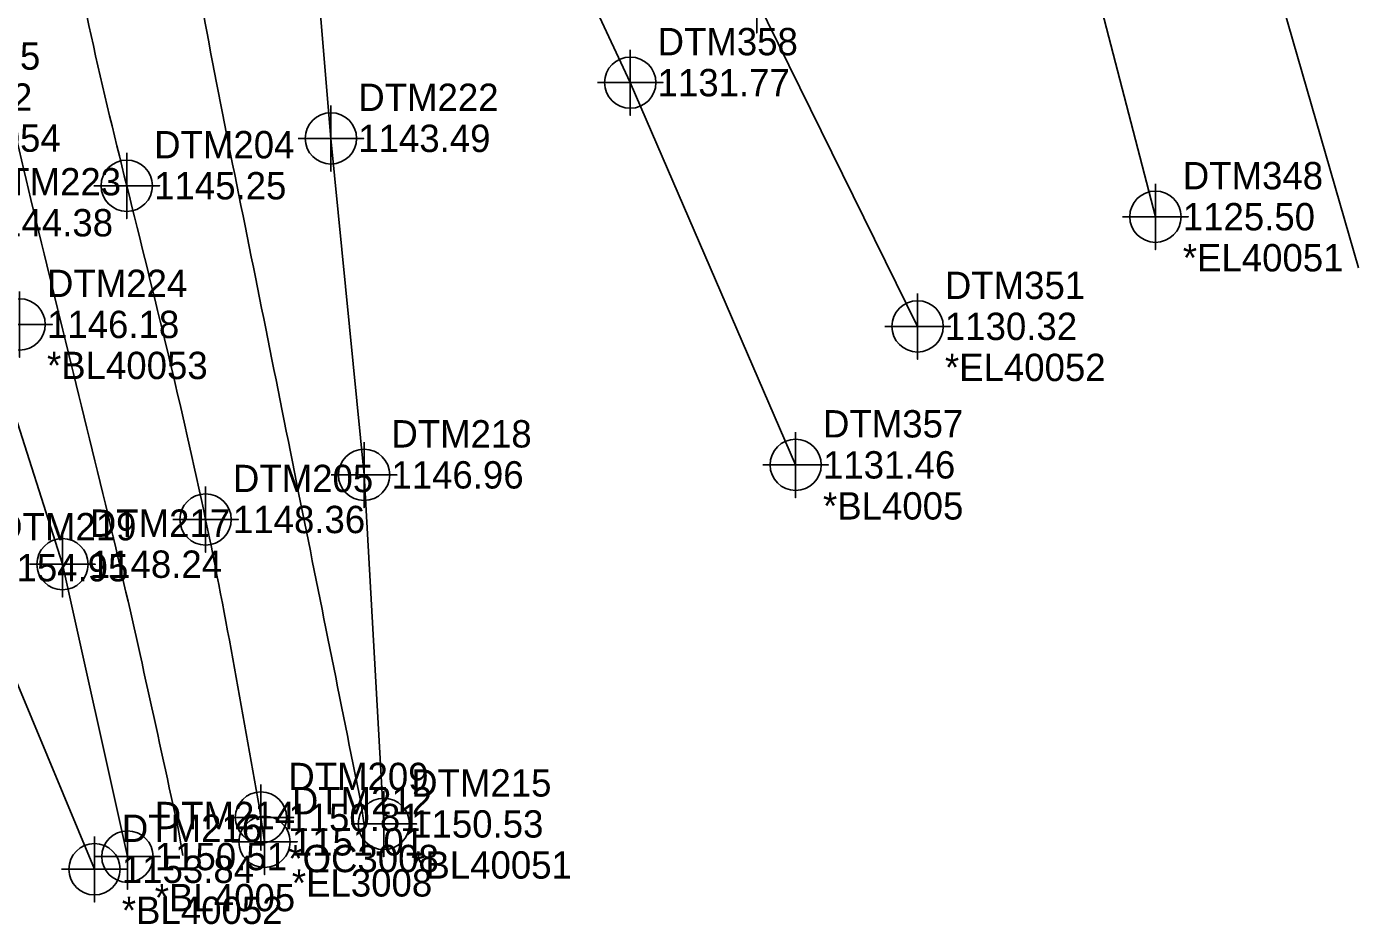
# Model space of a CAD drawing. Extents: x 1286409 to 1286829, y 857931 to 858308.
# Drawn here: x 1286511.7 to 1286633.4, y 857950.3 to 858032.3 of the extents above; entities that cross this region are included whole.
import ezdxf

# ---------------------------------------------------------------- set-up
doc = ezdxf.new("R2010")
doc.units = 0
for name, color, linetype in [('Exist DTM Breakline', 7, 'Continuous'), ('Exist DTM Breakline Cogo Comment', 7, 'Continuous'), ('Exist DTM Breakline Cogo Elevation', 7, 'Continuous'), ('Exist DTM Breakline Cogo Number', 7, 'Continuous'), ('Exist DTM Breakline Cogo Point CELL', 7, 'Continuous'), ('Exist DTM Crownline', 7, 'Continuous'), ('Exist DTM Crownline Cogo Comment', 7, 'Continuous'), ('Exist DTM Crownline Cogo Elevation', 7, 'Continuous'), ('Exist DTM Crownline Cogo Number', 7, 'Continuous'), ('Exist DTM Crownline Cogo Point CELL', 7, 'Continuous'), ('Exist Hydro Stream or Body of Water', 7, 'Continuous'), ('Exist Roads EOP', 7, 'Continuous')]:
    doc.layers.add(name, color=color, linetype=linetype)

msp = doc.modelspace()

# ---------------------------------------------------------------- linework, layer by layer
at = {"layer": 'Exist DTM Breakline'}
for points in [[(1286530.298, 858233.7), (1286543.261, 858195.881), (1286559.854, 858160.955), (1286563.292, 858147.427), (1286569.804, 858128.536), (1286569.528, 858112.107), (1286564.126, 858113.252), (1286558.412, 858113.755), (1286552.418, 858104.363), (1286554.757, 858095.462), (1286567.776, 858091.209), (1286569.105, 858068.653), (1286573.239, 858056.109), (1286586.738, 858049.307), (1286601.784, 858041.235), (1286607.702, 858042.424), (1286614.823, 858014.95)], [(1286520.872, 857956.475), (1286514.938, 857983.192), (1286504.975, 858014.397), (1286495.914, 858037.226), (1286486.828, 858061.942), (1286479.65, 858081.695), (1286469.24, 858100.695), (1286458.123, 858119.163), (1286445.852, 858131.468)], [(1286544.306, 857959.455), (1286542.498, 857991.356), (1286539.471, 858022.109), (1286538.051, 858038.904), (1286537.678, 858080.597), (1286539.403, 858085.731)], [(1286581.943, 857992.271), (1286566.826, 858027.199), (1286551.086, 858060.906), (1286539.718, 858085.149)], [(1286563.919, 858062.445), (1286578.38, 858034.745), (1286593.083, 858004.927)], [(1286517.862, 857955.312), (1286506.377, 857982.872), (1286493.003, 858017.794), (1286486.448, 857993.306), (1286467.899, 857993.131), (1286458.369, 858018.086), (1286470.547, 858031.105), (1286479.897, 858042.174), (1286469.015, 858060.288)]]:
    msp.add_lwpolyline(points, dxfattribs=at)
at = {"layer": 'Exist DTM Breakline Cogo Point CELL'}
for points in [[(1286578.38, 858037.745), (1286578.38, 858031.745), (1286578.38, 858034.745), (1286581.38, 858034.745), (1286575.38, 858034.745)], [(1286566.826, 858030.199), (1286566.826, 858024.199), (1286566.826, 858027.199), (1286569.826, 858027.199), (1286563.826, 858027.199)], [(1286539.471, 858025.109), (1286539.471, 858019.109), (1286539.471, 858022.109), (1286542.471, 858022.109), (1286536.471, 858022.109)], [(1286614.823, 858017.95), (1286614.823, 858011.95), (1286614.823, 858014.95), (1286617.823, 858014.95), (1286611.823, 858014.95)], [(1286511.023, 858008.106), (1286511.023, 858002.106), (1286511.023, 858005.106), (1286514.023, 858005.106), (1286508.023, 858005.106)], [(1286593.083, 858007.927), (1286593.083, 858001.927), (1286593.083, 858004.927), (1286596.083, 858004.927), (1286590.083, 858004.927)], [(1286542.498, 857994.356), (1286542.498, 857988.356), (1286542.498, 857991.356), (1286545.498, 857991.356), (1286539.498, 857991.356)], [(1286581.943, 857995.271), (1286581.943, 857989.271), (1286581.943, 857992.271), (1286584.943, 857992.271), (1286578.943, 857992.271)], [(1286514.938, 857986.192), (1286514.938, 857980.192), (1286514.938, 857983.192), (1286517.938, 857983.192), (1286511.938, 857983.192)], [(1286544.306, 857962.455), (1286544.306, 857956.455), (1286544.306, 857959.455), (1286547.306, 857959.455), (1286541.306, 857959.455)], [(1286520.872, 857959.475), (1286520.872, 857953.475), (1286520.872, 857956.475), (1286523.872, 857956.475), (1286517.872, 857956.475)], [(1286517.862, 857958.312), (1286517.862, 857952.312), (1286517.862, 857955.312), (1286520.862, 857955.312), (1286514.862, 857955.312)]]:
    msp.add_lwpolyline(points, dxfattribs=at)
for centre in [(1286566.826, 858027.199), (1286539.471, 858022.109), (1286614.823, 858014.95), (1286511.023, 858005.106), (1286593.083, 858004.927), (1286581.943, 857992.271), (1286542.498, 857991.356), (1286514.938, 857983.192), (1286544.306, 857959.455), (1286517.862, 857955.312), (1286520.872, 857956.475)]:
    msp.add_circle(centre, 2.344, dxfattribs=at)
at = {"layer": 'Exist DTM Crownline'}
msp.add_line((1286533.078, 857960.044), (1286533.401, 857957.819), dxfattribs=at)
msp.add_spline([(1286558.043, 858132.348), (1286548.721, 858127.222), (1286534.801, 858118.181), (1286523.71, 858102.686), (1286514.506, 858073.789), (1286514.745, 858047.233), (1286520.815, 858017.78), (1286528.017, 857987.278), (1286533.078, 857960.044)], degree=3, dxfattribs=at)
at = {"layer": 'Exist DTM Crownline Cogo Point CELL'}
for points in [[(1286520.815, 858020.78), (1286520.815, 858014.78), (1286520.815, 858017.78), (1286523.815, 858017.78), (1286517.815, 858017.78)], [(1286528.017, 857990.278), (1286528.017, 857984.278), (1286528.017, 857987.278), (1286531.017, 857987.278), (1286525.017, 857987.278)], [(1286533.078, 857963.044), (1286533.078, 857957.044), (1286533.078, 857960.044), (1286536.078, 857960.044), (1286530.078, 857960.044)], [(1286533.401, 857960.819), (1286533.401, 857954.819), (1286533.401, 857957.819), (1286536.401, 857957.819), (1286530.401, 857957.819)]]:
    msp.add_lwpolyline(points, dxfattribs=at)
for centre in [(1286520.815, 858017.78), (1286528.017, 857987.278), (1286533.078, 857960.044), (1286533.401, 857957.819)]:
    msp.add_circle(centre, 2.344, dxfattribs=at)
at = {"layer": 'Exist Hydro Stream or Body of Water'}
msp.add_lwpolyline([(1286633.369, 858010.272), (1286619.226, 858059.374), (1286604.574, 858088.843), (1286588.568, 858128.319), (1286577.591, 858159.308), (1286547.36, 858229.805), (1286531.042, 858265.146)], dxfattribs=at)
at = {"layer": 'Exist Roads EOP'}
for p, q in [((1286542.222, 857961.323), (1286542.518, 857959.301)), ((1286525.58, 857958.7), (1286525.934, 857956.558))]:
    msp.add_line(p, q, dxfattribs=at)
for points in [[(1286554.506, 858138.221), (1286544.419, 858134.401), (1286528.832, 858126.933), (1286512.047, 858109.768), (1286502.652, 858089.088), (1286501.393, 858072.897), (1286505.471, 858045.649), (1286512.056, 858016.522), (1286519.805, 857984.681), (1286525.58, 857958.7)], [(1286561.061, 858127.479), (1286553.633, 858121.854), (1286541.776, 858109.576), (1286533.023, 858097.553), (1286526.163, 858072.381), (1286525.732, 858049.679), (1286530.491, 858019.74), (1286536.523, 857989.722), (1286542.222, 857961.323)]]:
    msp.add_spline(points, degree=3, dxfattribs=at)

# ---------------------------------------------------------------- texts
at = {"layer": 'Exist DTM Breakline Cogo Comment'}
for s, p in [('*BL40054', (1286500.091, 858020.882)), ('*EL40051', (1286617.323, 858009.95)), ('*BL40053', (1286513.523, 858000.106)), ('*EL40052', (1286595.583, 857999.927)), ('*BL4005', (1286584.443, 857987.271)), ('*BL40051', (1286546.806, 857954.455)), ('*BL4005', (1286523.372, 857951.475)), ('*BL40052', (1286520.362, 857950.312))]:
    msp.add_text(s, height=2.5, dxfattribs=at).set_placement(p)
at = {"layer": 'Exist DTM Breakline Cogo Elevation'}
for s, p in [('1131.77', (1286569.326, 858025.949)), ('1143.72', (1286500.091, 858024.632)), ('1143.49', (1286541.971, 858020.859)), ('1125.50', (1286617.323, 858013.7)), ('1144.38', (1286507.475, 858013.147)), ('1146.18', (1286513.523, 858003.856)), ('1130.32', (1286595.583, 858003.677)), ('1131.46', (1286584.443, 857991.021)), ('1146.96', (1286544.998, 857990.106)), ('1148.24', (1286517.438, 857981.942)), ('1154.95', (1286508.877, 857981.622)), ('1150.53', (1286546.806, 857958.205)), ('1150.51', (1286523.372, 857955.225)), ('1153.84', (1286520.362, 857954.062))]:
    msp.add_text(s, height=2.5, dxfattribs=at).set_placement(p)
at = {"layer": 'Exist DTM Breakline Cogo Number'}
for s, p in [('DTM358', (1286569.326, 858029.699)), ('DTM225', (1286500.091, 858028.382)), ('DTM222', (1286541.971, 858024.609)), ('DTM348', (1286617.323, 858017.45)), ('DTM223', (1286507.475, 858016.897)), ('DTM224', (1286513.523, 858007.606)), ('DTM351', (1286595.583, 858007.427)), ('DTM357', (1286584.443, 857994.771)), ('DTM218', (1286544.998, 857993.856)), ('DTM217', (1286517.438, 857985.692)), ('DTM219', (1286508.877, 857985.372)), ('DTM215', (1286546.806, 857961.955)), ('DTM214', (1286523.372, 857958.975)), ('DTM216', (1286520.362, 857957.812))]:
    msp.add_text(s, height=2.5, dxfattribs=at).set_placement(p)
at = {"layer": 'Exist DTM Crownline Cogo Comment'}
for s, p in [('*OC3008', (1286535.578, 857955.044)), ('*EL3008', (1286535.901, 857952.819))]:
    msp.add_text(s, height=2.5, dxfattribs=at).set_placement(p)
at = {"layer": 'Exist DTM Crownline Cogo Elevation'}
for s, p in [('1145.25', (1286523.315, 858016.53)), ('1148.36', (1286530.517, 857986.028)), ('1150.81', (1286535.578, 857958.794)), ('1151.01', (1286535.901, 857956.569))]:
    msp.add_text(s, height=2.5, dxfattribs=at).set_placement(p)
at = {"layer": 'Exist DTM Crownline Cogo Number'}
for s, p in [('DTM204', (1286523.315, 858020.28)), ('DTM205', (1286530.517, 857989.778)), ('DTM209', (1286535.578, 857962.544)), ('DTM212', (1286535.901, 857960.319))]:
    msp.add_text(s, height=2.5, dxfattribs=at).set_placement(p)

doc.saveas('drawing.dxf')
